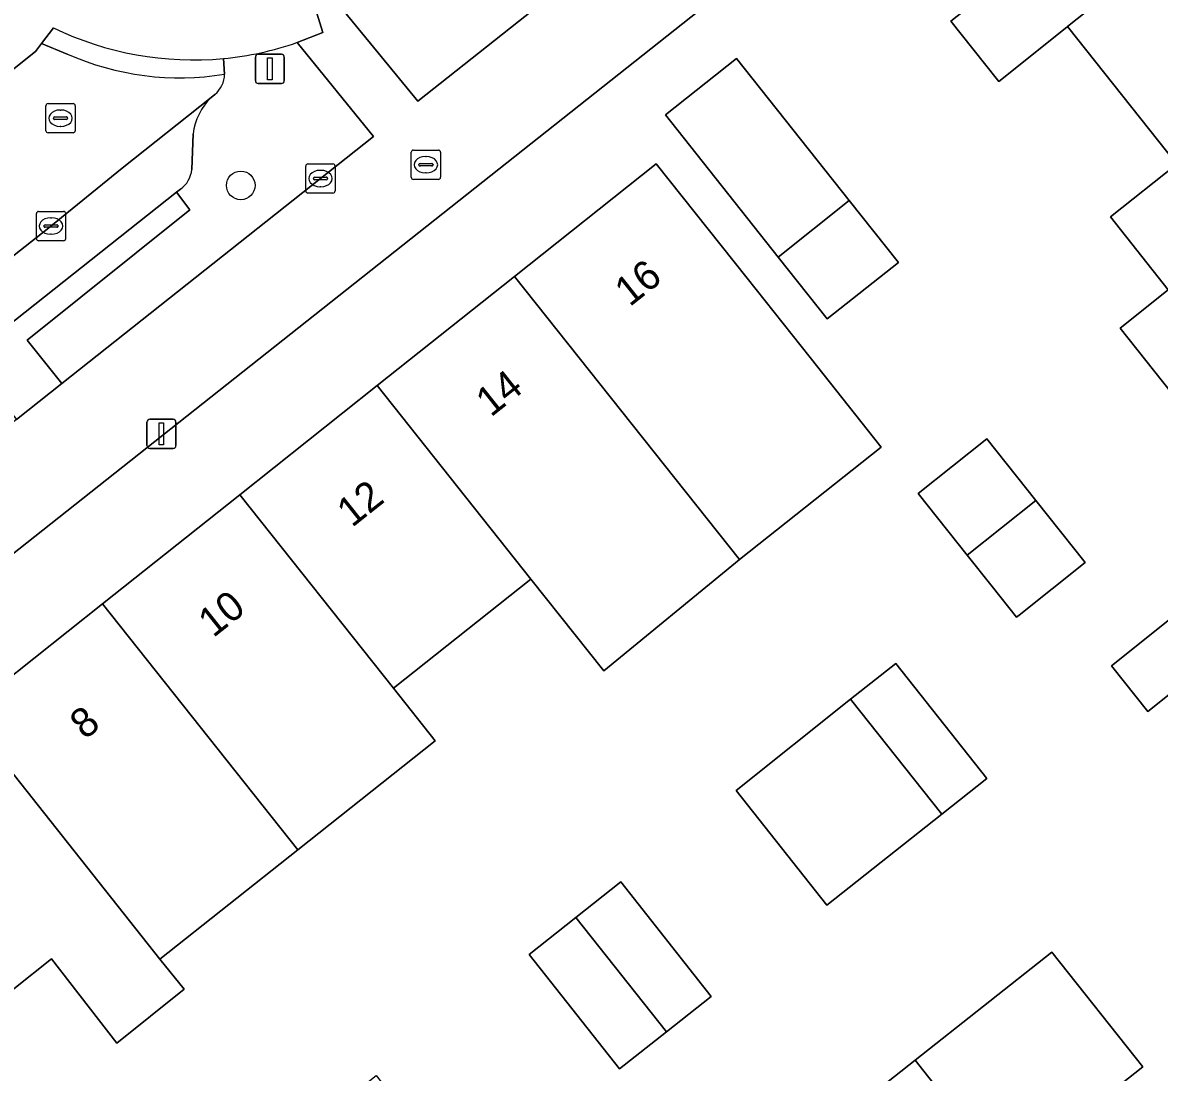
# Model space of a CAD drawing. Extents: x 157320 to 158835, y 386650 to 388491.
# Drawn here: x 157751.75 to 157790.58, y 387518.26 to 387554.12 of the extents above; entities that cross this region are included whole.
import ezdxf

# ---------------------------------------------------------------- set-up
doc = ezdxf.new("R2010")
doc.units = 0
for name, color, linetype in [('IMGEO_Boom', 7, 'Continuous'), ('IMGEO_Erf', 7, 'Continuous'), ('IMGEO_Groenvoorziening', 7, 'Continuous'), ('IMGEO_Kolk', 7, 'Continuous'), ('IMGEO_Lichtmast', 7, 'Continuous'), ('IMGEO_Pand', 7, 'Continuous'), ('IMGEO_Pand_nummerreeks', 7, 'Continuous'), ('IMGEO_Parkeervlak_open', 7, 'Continuous'), ('IMGEO_Rijbaan_lokaal_open', 7, 'Continuous'), ('IMGEO_Rioolput', 7, 'Continuous'), ('IMGEO_Voetpad_open', 7, 'Continuous')]:
    doc.layers.add(name, color=color, linetype=linetype)

msp = doc.modelspace()

# ---------------------------------------------------------------- linework, layer by layer
at = {"layer": 'IMGEO_Boom'}
msp.add_circle((157759.199, 387548.562), 0.489, dxfattribs=at)
at = {"layer": 'IMGEO_Erf'}
for points in [[(157819.244, 387513.872), (157824.278, 387517.873), (157829.287, 387521.854), (157827.412, 387524.212), (157792.348, 387568.39), (157742.039, 387528.565), (157744.071, 387526.007), (157755.546, 387511.564), (157757.331, 387512.983), (157759.693, 387514.861), (157761.245, 387516.095), (157763.827, 387518.148), (157766.927, 387514.234), (157764.333, 387512.18), (157762.786, 387510.955), (157760.42, 387509.082), (157758.638, 387507.671), (157762.365, 387502.98), (157760.625, 387501.492), (157769.911, 387489.771), (157777.254, 387480.504), (157788.46, 387489.409), (157801.788, 387500), (157809.599, 387506.206)], [(157779.241, 387543.998), (157777.563, 387546.111), (157773.707, 387550.968), (157776.14, 387552.899), (157779.993, 387548.046), (157781.674, 387545.929)], [(157754.969, 387519.263), (157752.733, 387522.137), (157750.15, 387520.087), (157744.928, 387526.688), (157749.769, 387530.534), (157754.47, 387534.268), (157759.163, 387537.996), (157763.855, 387541.724), (157768.549, 387545.452), (157773.398, 387549.304), (157776.507, 387545.389), (157778.656, 387542.68), (157781.084, 387539.619), (157776.243, 387535.777), (157776.104, 387535.667), (157771.603, 387531.978), (157769.114, 387535.108), (157764.419, 387531.383), (157765.844, 387529.59), (157761.145, 387525.864), (157756.438, 387522.13), (157757.263, 387521.1)], [(157785.792, 387533.878), (157785.706, 387533.81), (157784.873, 387534.858), (157784.018, 387535.934), (157782.35, 387538.035), (157784.697, 387539.9), (157786.366, 387537.799), (157788.054, 387535.675)], [(157790.198, 387530.591), (157788.95, 387532.154), (157792.866, 387535.279), (157794.114, 387533.715)], [(157783.155, 387527.085), (157779.225, 387523.973), (157776.125, 387527.887), (157780.038, 387531.005), (157781.578, 387532.232), (157784.691, 387528.302)], [(157772.14, 387518.379), (157769.055, 387522.288), (157770.646, 387523.548), (157772.187, 387524.769), (157775.277, 387520.854), (157773.747, 387519.647)], [(157780.62, 387511.023), (157779.228, 387509.922), (157779.854, 387509.13), (157776.542, 387506.511), (157776.267, 387506.859), (157772.816, 387511.221), (157777.52, 387514.94), (157782.241, 387518.673), (157786.913, 387522.368), (157790.017, 387518.454), (157785.336, 387514.752)]]:
    msp.add_lwpolyline(points, close=True, dxfattribs=at)
msp.add_lwpolyline([(157791.002, 387541.473), (157789.25, 387543.684), (157790.894, 387544.991), (157788.916, 387547.487), (157791.179, 387549.284), (157787.453, 387553.986), (157787.431, 387553.968), (157785.097, 387552.11), (157785.008, 387552.222), (157783.461, 387554.172), (157785.795, 387556.03), (157783.574, 387558.83), (157786.402, 387561.074), (157785.78, 387561.857), (157788.788, 387564.244), (157789.41, 387563.46), (157790.193, 387564.082), (157794.04, 387559.231)], dxfattribs=at)
at = {"layer": 'IMGEO_Groenvoorziening'}
msp.add_lwpolyline([(157761.225, 387556.351), (157765.248, 387551.437), (157770.763, 387555.81), (157767.202, 387560.196), (157766.892, 387560.528), (157764.379, 387558.484), (157762.696, 387557.144), (157761.883, 387556.651)], close=True, dxfattribs=at)
for points in [[(157757.135, 387548.437), (157756.999, 387548.33), (157757.453, 387547.729), (157751.905, 387543.275), (157753.086, 387541.793), (157763.733, 387550.236), (157761.12, 387553.441)], [(157758.609, 387552.898), (157758.644, 387552.362)], [(157758.315, 387551.667), (157758.189, 387551.567)], [(157757.57, 387550.319), (157757.524, 387549.105)]]:
    msp.add_lwpolyline(points, dxfattribs=at)
for centre, radius, start, end in [((157757.587, 387563.7), 10.85, 275.4031, 289.0013), ((157757.717, 387552.376), 0.928, 310.1814, 359.1546), ((157759.639, 387550.07), 2.084, 134.0921, 173.1457), ((157756.636, 387549.175), 0.891, 304.0628, 355.5097)]:
    msp.add_arc(centre, radius, start, end, dxfattribs=at)
at = {"layer": 'IMGEO_Kolk'}
for p, q in [((157761.42, 387548.371), (157761.42, 387549.223)), ((157761.495, 387549.297), (157762.347, 387549.297)), ((157761.908, 387549.077), (157761.933, 387549.077)), ((157762.421, 387549.223), (157762.421, 387548.371)), ((157761.679, 387548.791), (157761.679, 387548.803)), ((157762.117, 387548.754), (157761.719, 387548.754)), ((157761.722, 387548.84), (157762.12, 387548.84)), ((157762.163, 387548.803), (157762.163, 387548.791)), ((157762.347, 387548.297), (157761.495, 387548.297)), ((157761.931, 387548.517), (157761.906, 387548.517)), ((157752.214, 387546.748), (157752.214, 387547.6)), ((157752.289, 387547.674), (157753.141, 387547.674)), ((157753.215, 387547.6), (157753.215, 387546.748)), ((157752.473, 387547.168), (157752.473, 387547.18)), ((157752.911, 387547.131), (157752.513, 387547.131)), ((157752.516, 387547.217), (157752.914, 387547.217)), ((157752.702, 387547.454), (157752.727, 387547.454)), ((157752.957, 387547.18), (157752.957, 387547.168)), ((157752.725, 387546.894), (157752.7, 387546.894)), ((157753.141, 387546.674), (157752.289, 387546.674))]:
    msp.add_line(p, q, dxfattribs=at)
for points in [[(157761.42, 387548.371), (157761.42, 387549.223)], [(157761.495, 387549.297), (157762.347, 387549.297)], [(157762.421, 387549.223), (157762.421, 387548.371)], [(157762.347, 387548.297), (157761.495, 387548.297)], [(157752.214, 387546.748), (157752.214, 387547.6)], [(157752.289, 387547.674), (157753.141, 387547.674)], [(157753.215, 387547.6), (157753.215, 387546.748)], [(157753.141, 387546.674), (157752.289, 387546.674)]]:
    msp.add_lwpolyline(points, dxfattribs=at)
for centre, radius, start, end in [((157761.497, 387549.221), 0.0765, 91.552, 178.448), ((157761.497, 387549.221), 0.0765, 91.552, 178.448), ((157762.345, 387549.221), 0.0765, 1.552, 88.448), ((157762.345, 387549.221), 0.0765, 1.552, 88.448), ((157761.719, 387548.8), 0.0403, 85.8775, 175.7526), ((157761.716, 387548.79), 0.0366, 178.938, 274.7102), ((157762.12, 387548.797), 0.043, 264.8664, 352.4533), ((157762.124, 387548.802), 0.0386, 1.7309, 96.639), ((157761.497, 387548.373), 0.0765, 181.552, 268.448), ((157761.497, 387548.373), 0.0765, 181.552, 268.448), ((157762.345, 387548.373), 0.0765, 271.552, 358.448), ((157762.345, 387548.373), 0.0765, 271.552, 358.448), ((157752.291, 387547.598), 0.0765, 91.552, 178.448), ((157752.291, 387547.598), 0.0765, 91.552, 178.448), ((157753.139, 387547.598), 0.0765, 1.552, 88.448), ((157753.139, 387547.598), 0.0765, 1.552, 88.448), ((157752.513, 387547.177), 0.0403, 85.8775, 175.7526), ((157752.51, 387547.167), 0.0366, 178.938, 274.7102), ((157752.914, 387547.174), 0.043, 264.8664, 352.4533), ((157752.918, 387547.179), 0.0386, 1.7309, 96.639), ((157752.291, 387546.75), 0.0765, 181.552, 268.448), ((157752.291, 387546.75), 0.0765, 181.552, 268.448), ((157753.139, 387546.75), 0.0765, 271.552, 358.448), ((157753.139, 387546.75), 0.0765, 271.552, 358.448)]:
    msp.add_arc(centre, radius, start, end, dxfattribs=at)
for centre, major_axis, ratio, start_param, end_param in [((157761.907, 387548.797), (-0.387, 0.002), 0.722429, 4.712389, 7.853982), ((157761.932, 387548.797), (-0.39, 0.002), 0.717154, 1.570796, 4.712389), ((157752.701, 387547.174), (-0.387, 0.002), 0.722429, 4.712389, 7.853982), ((157752.726, 387547.174), (-0.39, 0.002), 0.717154, 1.570796, 4.712389)]:
    msp.add_ellipse(centre, major_axis=major_axis, ratio=ratio, start_param=start_param, end_param=end_param, dxfattribs=at)
at = {"layer": 'IMGEO_Lichtmast'}
for p, q in [((157759.697, 387552.142), (157759.697, 387552.942)), ((157759.697, 387552.942), (157759.697, 387552.142)), ((157759.797, 387553.042), (157760.587, 387553.042)), ((157760.587, 387553.042), (157759.797, 387553.042)), ((157760.687, 387552.942), (157760.687, 387552.142)), ((157760.687, 387552.142), (157760.687, 387552.942)), ((157760.587, 387552.042), (157759.797, 387552.042)), ((157759.797, 387552.042), (157760.587, 387552.042)), ((157756.093, 387540.574), (157756.883, 387540.574)), ((157756.883, 387540.574), (157756.093, 387540.574)), ((157755.993, 387539.674), (157755.993, 387540.474)), ((157755.993, 387540.474), (157755.993, 387539.674)), ((157756.983, 387540.474), (157756.983, 387539.674)), ((157756.983, 387539.674), (157756.983, 387540.474)), ((157756.883, 387539.574), (157756.093, 387539.574)), ((157756.093, 387539.574), (157756.883, 387539.574))]:
    msp.add_line(p, q, dxfattribs=at)
for points in [[(157760.117, 387552.917), (157760.267, 387552.917), (157760.267, 387552.167), (157760.117, 387552.167), (157760.117, 387552.917)], [(157756.413, 387540.449), (157756.563, 387540.449), (157756.563, 387539.699), (157756.413, 387539.699), (157756.413, 387540.449)]]:
    msp.add_lwpolyline(points, dxfattribs=at)
for centre, start, end in [((157759.797, 387552.942), 90, 180), ((157759.797, 387552.942), 90, 180), ((157760.587, 387552.942), 0, 90), ((157760.587, 387552.942), 360, 90), ((157759.797, 387552.142), 180, 270), ((157759.797, 387552.142), 180, 270), ((157760.587, 387552.142), 270, 0), ((157760.587, 387552.142), 270, 0), ((157756.093, 387540.474), 90, 180), ((157756.093, 387540.474), 90, 180), ((157756.883, 387540.474), 0, 90), ((157756.883, 387540.474), 360, 90), ((157756.093, 387539.674), 180, 270), ((157756.093, 387539.674), 180, 270), ((157756.883, 387539.674), 270, 0), ((157756.883, 387539.674), 270, 0)]:
    msp.add_arc(centre, 0.1, start, end, dxfattribs=at)
at = {"layer": 'IMGEO_Pand'}
for points in [[(157790.193, 387564.082), (157789.41, 387563.46), (157788.788, 387564.244), (157785.78, 387561.857), (157786.402, 387561.074), (157783.574, 387558.83), (157785.795, 387556.03), (157783.461, 387554.172), (157785.008, 387552.222), (157785.097, 387552.11), (157787.431, 387553.968), (157787.453, 387553.986), (157794.04, 387559.231)], [(157791.179, 387549.284), (157797.776, 387554.523), (157794.04, 387559.231), (157787.453, 387553.986)], [(157801.506, 387549.824), (157797.776, 387554.523), (157791.179, 387549.284), (157788.916, 387547.487), (157790.894, 387544.991), (157789.25, 387543.684), (157791.002, 387541.473)], [(157777.563, 387546.111), (157779.993, 387548.046), (157776.14, 387552.899), (157773.707, 387550.968)], [(157776.243, 387535.777), (157781.084, 387539.619), (157778.656, 387542.68), (157776.507, 387545.389), (157773.398, 387549.304), (157768.549, 387545.452)], [(157777.563, 387546.111), (157779.241, 387543.998), (157781.674, 387545.929), (157779.993, 387548.046)], [(157776.243, 387535.777), (157768.549, 387545.452), (157763.855, 387541.724), (157769.114, 387535.108), (157771.603, 387531.978), (157776.104, 387535.667)], [(157759.163, 387537.996), (157764.419, 387531.383), (157769.114, 387535.108), (157763.855, 387541.724)], [(157786.366, 387537.799), (157784.697, 387539.9), (157782.35, 387538.035), (157784.018, 387535.934)], [(157754.47, 387534.268), (157761.145, 387525.864), (157765.844, 387529.59), (157764.419, 387531.383), (157759.163, 387537.996)], [(157788.054, 387535.675), (157786.366, 387537.799), (157784.018, 387535.934), (157784.873, 387534.858), (157785.706, 387533.81), (157785.792, 387533.878)], [(157790.198, 387530.591), (157794.114, 387533.715), (157792.866, 387535.279), (157788.95, 387532.154)], [(157749.769, 387530.534), (157756.438, 387522.13), (157761.145, 387525.864), (157754.47, 387534.268)], [(157780.038, 387531.005), (157783.155, 387527.085), (157784.691, 387528.302), (157781.578, 387532.232)], [(157780.038, 387531.005), (157776.125, 387527.887), (157779.225, 387523.973), (157783.155, 387527.085)], [(157749.769, 387530.534), (157744.928, 387526.688), (157750.15, 387520.087), (157752.733, 387522.137), (157754.969, 387519.263), (157757.263, 387521.1), (157756.438, 387522.13)], [(157772.187, 387524.769), (157770.646, 387523.548), (157773.747, 387519.647), (157775.277, 387520.854)], [(157770.646, 387523.548), (157769.055, 387522.288), (157772.14, 387518.379), (157773.747, 387519.647)], [(157790.017, 387518.454), (157786.913, 387522.368), (157782.241, 387518.673), (157785.336, 387514.752)], [(157780.62, 387511.023), (157785.336, 387514.752), (157782.241, 387518.673), (157777.52, 387514.94)]]:
    msp.add_lwpolyline(points, close=True, dxfattribs=at)
at = {"layer": 'IMGEO_Parkeervlak_open'}
for points in [[(157758.189, 387551.567), (157755.146, 387549.153), (157752.579, 387547.065), (157741.509, 387538.353), (157739.533, 387536.755)], [(157757.524, 387549.105), (157757.57, 387550.319)], [(157742.943, 387537.189), (157743.132, 387537.339), (157756.999, 387548.33), (157757.135, 387548.437)]]:
    msp.add_lwpolyline(points, dxfattribs=at)
for centre, radius, start, end in [((157759.639, 387550.07), 2.084, 134.0921, 173.1457), ((157756.636, 387549.175), 0.891, 304.0628, 355.5097)]:
    msp.add_arc(centre, radius, start, end, dxfattribs=at)
at = {"layer": 'IMGEO_Rijbaan_lokaal_open'}
for points in [[(157753.272, 387553.05), (157752.394, 387553.414), (157752.186, 387553.14), (157750.654, 387551.925), (157748.929, 387550.558), (157736.667, 387540.966), (157734.138, 387538.975), (157729.283, 387535.274), (157720.481, 387528.275), (157705.883, 387516.885), (157692.28, 387506.153)], [(157723.417, 387524.199), (157732.871, 387531.591), (157738.106, 387535.707), (157739.533, 387536.755), (157741.509, 387538.353), (157752.579, 387547.065), (157755.146, 387549.153), (157758.189, 387551.567), (157758.315, 387551.667)]]:
    msp.add_lwpolyline(points, dxfattribs=at)
for centre, radius, start, end in [((157757.112, 387561.713), 9.476, 246.0964, 279.3072), ((157757.717, 387552.376), 0.928, 310.1814, 359.1546)]:
    msp.add_arc(centre, radius, start, end, dxfattribs=at)
at = {"layer": 'IMGEO_Rioolput'}
for p, q in [((157752.614, 387551.358), (157753.466, 387551.358)), ((157752.539, 387550.432), (157752.539, 387551.284)), ((157753.027, 387551.138), (157753.052, 387551.138)), ((157753.54, 387551.284), (157753.54, 387550.432)), ((157752.798, 387550.852), (157752.798, 387550.864)), ((157753.236, 387550.815), (157752.838, 387550.815)), ((157752.841, 387550.901), (157753.239, 387550.901)), ((157753.05, 387550.578), (157753.025, 387550.578)), ((157753.282, 387550.864), (157753.282, 387550.852)), ((157753.466, 387550.358), (157752.614, 387550.358)), ((157765.025, 387548.842), (157765.025, 387549.694)), ((157765.1, 387549.768), (157765.952, 387549.768)), ((157765.513, 387549.548), (157765.538, 387549.548)), ((157766.026, 387549.694), (157766.026, 387548.842)), ((157765.284, 387549.262), (157765.284, 387549.274)), ((157765.722, 387549.225), (157765.324, 387549.225)), ((157765.327, 387549.311), (157765.725, 387549.311)), ((157765.768, 387549.274), (157765.768, 387549.262)), ((157765.952, 387548.768), (157765.1, 387548.768)), ((157765.536, 387548.988), (157765.511, 387548.988))]:
    msp.add_line(p, q, dxfattribs=at)
for points in [[(157752.614, 387551.358), (157753.466, 387551.358)], [(157752.539, 387550.432), (157752.539, 387551.284)], [(157753.54, 387551.284), (157753.54, 387550.432)], [(157753.466, 387550.358), (157752.614, 387550.358)], [(157765.025, 387548.842), (157765.025, 387549.694)], [(157765.1, 387549.768), (157765.952, 387549.768)], [(157766.026, 387549.694), (157766.026, 387548.842)], [(157765.952, 387548.768), (157765.1, 387548.768)]]:
    msp.add_lwpolyline(points, dxfattribs=at)
for centre, radius, start, end in [((157752.616, 387551.282), 0.0765, 91.552, 178.448), ((157752.616, 387551.282), 0.0765, 91.552, 178.448), ((157753.464, 387551.282), 0.0765, 1.552, 88.448), ((157753.464, 387551.282), 0.0765, 1.552, 88.448), ((157752.838, 387550.861), 0.0403, 85.8775, 175.7526), ((157752.835, 387550.851), 0.0366, 178.938, 274.7102), ((157753.239, 387550.858), 0.043, 264.8664, 352.4533), ((157753.243, 387550.863), 0.0386, 1.7309, 96.639), ((157752.616, 387550.434), 0.0765, 181.552, 268.448), ((157752.616, 387550.434), 0.0765, 181.552, 268.448), ((157753.464, 387550.434), 0.0765, 271.552, 358.448), ((157753.464, 387550.434), 0.0765, 271.552, 358.448), ((157765.102, 387549.692), 0.0765, 91.552, 178.448), ((157765.102, 387549.692), 0.0765, 91.552, 178.448), ((157765.95, 387549.692), 0.0765, 1.552, 88.448), ((157765.95, 387549.692), 0.0765, 1.552, 88.448), ((157765.324, 387549.271), 0.0403, 85.8775, 175.7526), ((157765.321, 387549.261), 0.0366, 178.938, 274.7102), ((157765.725, 387549.268), 0.043, 264.8664, 352.4533), ((157765.729, 387549.273), 0.0386, 1.7309, 96.639), ((157765.102, 387548.844), 0.0765, 181.552, 268.448), ((157765.102, 387548.844), 0.0765, 181.552, 268.448), ((157765.95, 387548.844), 0.0765, 271.552, 358.448), ((157765.95, 387548.844), 0.0765, 271.552, 358.448)]:
    msp.add_arc(centre, radius, start, end, dxfattribs=at)
for centre, major_axis, ratio, start_param, end_param in [((157753.026, 387550.858), (-0.387, 0.002), 0.722429, 4.712389, 7.853982), ((157753.051, 387550.858), (-0.39, 0.002), 0.717154, 1.570796, 4.712389), ((157765.512, 387549.268), (-0.387, 0.002), 0.722429, 4.712389, 7.853982), ((157765.537, 387549.268), (-0.39, 0.002), 0.717154, 1.570796, 4.712389)]:
    msp.add_ellipse(centre, major_axis=major_axis, ratio=ratio, start_param=start_param, end_param=end_param, dxfattribs=at)
at = {"layer": 'IMGEO_Voetpad_open'}
for points in [[(157714.825, 387618.222), (157714.525, 387618.81), (157713.606, 387618.322), (157711.124, 387622.997), (157710.561, 387622.698), (157710.003, 387622.401), (157712.088, 387618.361), (157711.546, 387618.057), (157712.78, 387615.384), (157715.302, 387610.401), (157719.417, 387602.787), (157727.739, 387587.082), (157728.437, 387585.765), (157731.431, 387580.114), (157730.809, 387577.363), (157746.726, 387556.998), (157749.611, 387553.306), (157750.654, 387551.925), (157752.186, 387553.14), (157752.394, 387553.414), (157752.798, 387553.945)], [(157761.544, 387555.262), (157762.004, 387553.788), (157761.12, 387553.441), (157763.733, 387550.236), (157753.086, 387541.793), (157751.53, 387540.559), (157740.906, 387532.135), (157738.803, 387534.802), (157738.741, 387534.883), (157733.507, 387530.768), (157733.522, 387530.749), (157735.667, 387528.041), (157700.195, 387500), (157693.756, 387494.91), (157692.652, 387494.004), (157694.258, 387491.516), (157695.265, 387492.316), (157700.679, 387496.618), (157703.815, 387499.11), (157704.936, 387500), (157738.441, 387526.62), (157738.866, 387526.111), (157742.039, 387528.565), (157792.348, 387568.39)], [(157770.763, 387555.81), (157765.248, 387551.437), (157761.225, 387556.351)], [(157761.12, 387553.441), (157762.004, 387553.788), (157761.544, 387555.262), (157761.523, 387555.33)], [(157752.798, 387553.945), (157752.394, 387553.414), (157753.272, 387553.05)], [(157758.644, 387552.362), (157758.609, 387552.898)]]:
    msp.add_lwpolyline(points, dxfattribs=at)
msp.add_lwpolyline([(157743.132, 387537.339), (157743.631, 387536.751), (157750.365, 387542.06), (157751.53, 387540.559), (157753.086, 387541.793), (157751.905, 387543.275), (157757.453, 387547.729), (157756.999, 387548.33)], close=True, dxfattribs=at)
for centre, radius, start, end in [((157757.572, 387563.79), 10.941, 244.1316, 275.441), ((157757.572, 387563.79), 10.941, 244.1316, 275.441), ((157757.587, 387563.7), 10.85, 275.4031, 289.0013), ((157757.112, 387561.713), 9.476, 246.0964, 279.3072)]:
    msp.add_arc(centre, radius, start, end, dxfattribs=at)

# ---------------------------------------------------------------- texts
at = {"layer": 'IMGEO_Pand_nummerreeks'}
for s, p in [('16', (157772.489, 387544.394)), ('14', (157767.744, 387540.624)), ('12', (157762.997, 387536.853)), ('10', (157758.257, 387533.088)), ('8', (157753.873, 387529.605))]:
    msp.add_text(s, height=1, rotation=38.4629, dxfattribs=at).set_placement(p)

doc.saveas('drawing.dxf')
